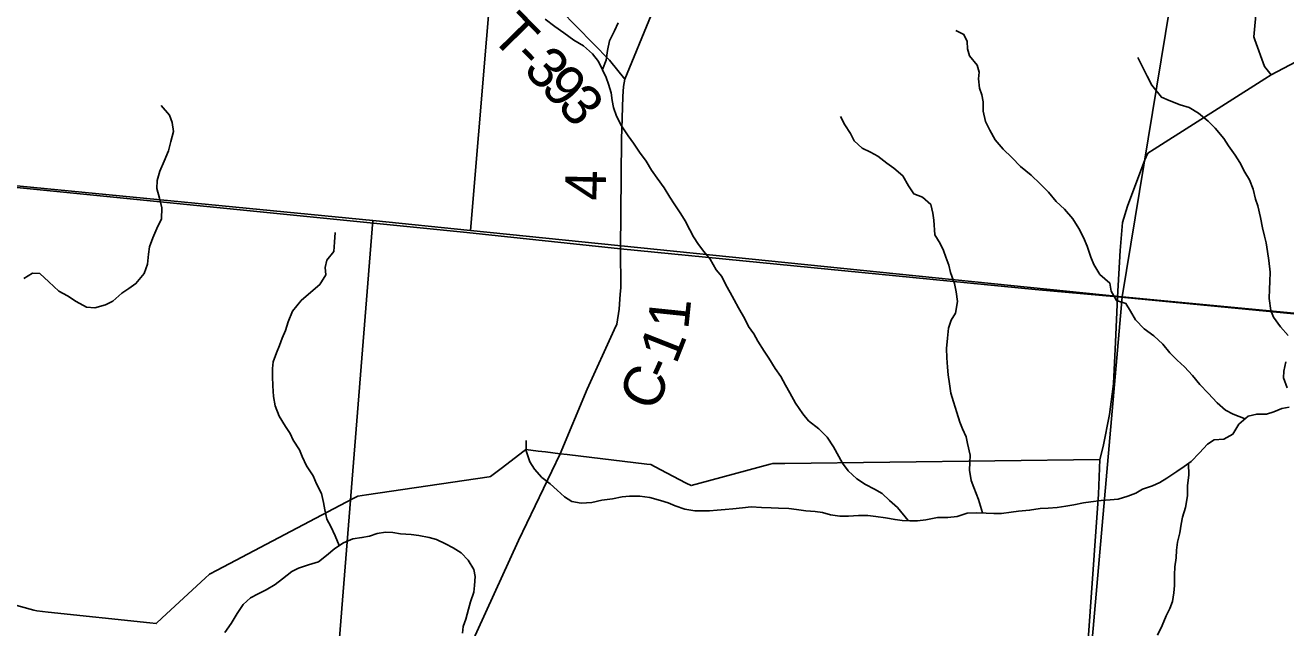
# Model space of a CAD drawing. Extents: x 0 to 42, y 0 to 22.
# Drawn here: x 2.271 to 3.149, y 16.454 to 16.874 of the extents above; entities that cross this region are included whole.
import ezdxf

# ---------------------------------------------------------------- set-up
doc = ezdxf.new("R2010")
doc.units = 0
for name, color, linetype in [('GM_X_County_Road', 7, 'Continuous'), ('GM_X_County_Road_Text', 7, 'Continuous'), ('GM_X_Minor_River', 7, 'Continuous'), ('GM_X_Section', 7, 'Continuous'), ('GM_X_Township_Road', 7, 'Continuous'), ('GM_X_Township_Road_Text', 7, 'Continuous'), ('GM_X_Unincorporated', 7, 'Continuous')]:
    doc.layers.add(name, color=color, linetype=linetype)

msp = doc.modelspace()

# ---------------------------------------------------------------- linework, layer by layer
at = {"layer": 'GM_X_County_Road'}
for points in [[(3.13844, 16.83963), (3.13371, 16.84527), (3.12716, 16.86391), (3.12645, 16.86593), (3.12717, 16.87363), (3.13317, 16.93756), (3.13328, 16.93883), (3.12484, 16.94043), (3.07632, 16.94963), (3.0777, 16.95929), (3.11773, 17.21473), (2.99607, 17.21011), (2.99103, 17.2099)], [(2.68511, 16.68671), (2.68545, 16.69114), (2.68536, 16.71812), (2.68602, 16.79453), (2.68687, 16.82435), (2.68744, 16.83145), (2.68835, 16.83654), (2.72497, 16.92595)], [(3.50756, 16.63162), (3.49853, 16.63934), (3.44232, 16.68624), (3.3385, 16.77134), (3.33566, 16.77384), (3.33464, 16.77987), (3.3173, 16.88212), (3.31708, 16.88339), (3.31183, 16.89018), (3.29373, 16.91364), (3.28943, 16.91921), (3.28257, 16.91567), (3.13844, 16.83963)], [(3.02838, 16.62254), (3.02865, 16.62454), (3.03004, 16.65342), (3.03147, 16.68469), (3.03318, 16.71722), (3.03483, 16.73675), (3.0384, 16.74804), (3.05044, 16.78036), (3.05248, 16.78486), (3.05688, 16.78766), (3.13403, 16.83681), (3.13844, 16.83963)], [(2.56825, 16.41433), (2.61413, 16.51522), (2.64333, 16.57563), (2.66209, 16.6207), (2.68086, 16.66198), (2.6826, 16.66583), (2.68431, 16.67637), (2.68511, 16.68671)], [(2.64333, 16.57563), (2.64821, 16.57505), (2.70371, 16.5684), (2.7065, 16.56806), (2.71301, 16.56465), (2.73101, 16.55521), (2.73439, 16.55344), (2.74052, 16.5551), (2.78958, 16.56836), (2.79129, 16.56882), (2.79967, 16.56886), (3.01914, 16.57163), (3.02134, 16.58071), (3.02575, 16.603), (3.02838, 16.62254)], [(2.18354, 16.49212), (2.27669, 16.46667), (2.27878, 16.4661), (2.28671, 16.46526), (2.35747, 16.45783), (2.36186, 16.45737), (2.36607, 16.46126), (2.39593, 16.48886), (2.39904, 16.49173), (2.40428, 16.49449), (2.49872, 16.5442), (2.50222, 16.54603), (2.50834, 16.54694), (2.59381, 16.55957), (2.59478, 16.5597), (2.60207, 16.56526), (2.61824, 16.57759), (2.61944, 16.5785), (2.62803, 16.57747), (2.63307, 16.57687), (2.64333, 16.57563)], [(3.15556, 16.07734), (3.11596, 16.08209), (3.10775, 16.08373), (3.09954, 16.08683), (3.08329, 16.09723), (3.06213, 16.11584), (3.04041, 16.13263), (3.01849, 16.15304), (2.99402, 16.18319), (2.97659, 16.20462), (2.94677, 16.24432), (2.92682, 16.26806), (2.92495, 16.27329), (2.92703, 16.28318), (2.9369, 16.30146), (2.94257, 16.3107), (2.94845, 16.31763), (2.99745, 16.36645), (3.0023, 16.37263), (3.00466, 16.37925), (3.00554, 16.38588), (3.00939, 16.42316), (3.01821, 16.54744), (3.01914, 16.57163)]]:
    msp.add_lwpolyline(points, dxfattribs=at)
at = {"layer": 'GM_X_Minor_River'}
for points in [[(2.88555, 16.52904), (2.87826, 16.53812), (2.87261, 16.54307), (2.86752, 16.54782), (2.86223, 16.55087), (2.85582, 16.55412), (2.84978, 16.55812), (2.84393, 16.56364), (2.83998, 16.56896), (2.83359, 16.58035), (2.82927, 16.58719), (2.82343, 16.59289), (2.81626, 16.59842), (2.8123, 16.60336), (2.80722, 16.61076), (2.80328, 16.61798), (2.80008, 16.6233), (2.79689, 16.62937), (2.79294, 16.63507), (2.78862, 16.6421), (2.78523, 16.64704), (2.7809, 16.65406), (2.77809, 16.65919), (2.77432, 16.66413), (2.77188, 16.66963), (2.76756, 16.67723), (2.76455, 16.68273), (2.76155, 16.68786), (2.75854, 16.69337), (2.75573, 16.69906), (2.75196, 16.70381), (2.74764, 16.71122), (2.74331, 16.71654), (2.73954, 16.72129), (2.73616, 16.72661), (2.73353, 16.73155), (2.73033, 16.73781), (2.72733, 16.74275), (2.72262, 16.74958), (2.71961, 16.75433), (2.71567, 16.76079), (2.71077, 16.76763), (2.70682, 16.77314), (2.70306, 16.77941), (2.69855, 16.78568), (2.69441, 16.79194), (2.69064, 16.79708), (2.68594, 16.80391), (2.68256, 16.81075), (2.68031, 16.81682), (2.67957, 16.82156), (2.67884, 16.82706), (2.67697, 16.83294), (2.67528, 16.83768), (2.67284, 16.84299), (2.66984, 16.84869), (2.6657, 16.8542), (2.65948, 16.85972), (2.65287, 16.86373), (2.6457, 16.86887), (2.63948, 16.87325), (2.63269, 16.8782)], [(2.67267, 16.84333), (2.67533, 16.84981), (2.6763, 16.85644), (2.67765, 16.86325), (2.68108, 16.87006), (2.68375, 16.87573)], [(3.12037, 16.59997), (3.11192, 16.60316), (3.10663, 16.60602), (3.10079, 16.61097), (3.09457, 16.61782), (3.08873, 16.6239), (3.08365, 16.63017), (3.07818, 16.63626), (3.0729, 16.64082), (3.06782, 16.64596), (3.06292, 16.65204), (3.0567, 16.65775), (3.0501, 16.66251), (3.04388, 16.66898), (3.0405, 16.67486), (3.0373, 16.68037), (3.03069, 16.68229), (3.02712, 16.68893), (3.026, 16.69443), (3.01922, 16.70052), (3.01489, 16.70736), (3.01283, 16.71248), (3.01021, 16.72007), (3.00777, 16.72614), (3.00439, 16.73241), (3.00026, 16.73924), (2.99461, 16.74589), (2.98876, 16.75122), (2.9833, 16.75768), (2.97765, 16.76358), (2.97124, 16.76967), (2.96389, 16.77576), (2.95786, 16.78203), (2.95183, 16.78774), (2.94618, 16.7942), (2.94242, 16.80104), (2.93941, 16.80711), (2.93793, 16.81413), (2.93795, 16.82076), (2.93683, 16.8255), (2.93534, 16.83024), (2.93461, 16.83669), (2.935, 16.84142), (2.9337, 16.84635), (2.92843, 16.85282), (2.92693, 16.85756), (2.92676, 16.86268), (2.92451, 16.86761), (2.91884, 16.87047)], [(3.15033, 16.65796), (3.14506, 16.66404), (3.13997, 16.67069), (3.13829, 16.67543), (3.137, 16.68378), (3.13721, 16.69022), (3.13742, 16.69552), (3.13782, 16.70215), (3.13691, 16.71011), (3.13598, 16.71637), (3.13487, 16.72243), (3.13375, 16.72717), (3.13245, 16.73286), (3.13096, 16.74007), (3.1291, 16.74822), (3.12761, 16.75296), (3.12593, 16.75998), (3.12331, 16.76643), (3.12011, 16.77175), (3.11654, 16.77839), (3.11335, 16.78352), (3.10864, 16.79017), (3.10544, 16.79511), (3.09942, 16.80233), (3.09452, 16.80728), (3.08792, 16.8128), (3.08131, 16.8168), (3.07508, 16.81853), (3.06733, 16.82159), (3.06205, 16.82407), (3.05527, 16.83225), (3.05208, 16.83851), (3.0487, 16.84553), (3.04569, 16.85161)], [(2.37309, 16.80624), (2.37122, 16.81137), (2.36538, 16.81821)], [(2.2696, 16.69769), (2.27567, 16.70145), (2.28078, 16.70124), (2.287, 16.69535), (2.29397, 16.68888), (2.3002, 16.68563), (2.30624, 16.68163), (2.31341, 16.67781), (2.31909, 16.67722), (2.32666, 16.67928), (2.33159, 16.68191), (2.33804, 16.68738), (2.34278, 16.69078), (2.34771, 16.69417), (2.35341, 16.70116), (2.35589, 16.70759), (2.35649, 16.7146), (2.35726, 16.71971), (2.35955, 16.72596), (2.36242, 16.73239), (2.36547, 16.7392), (2.36569, 16.74677), (2.3642, 16.7536), (2.36233, 16.76043), (2.36254, 16.76592), (2.36446, 16.77236), (2.36751, 16.77936), (2.37056, 16.78655), (2.3721, 16.79317), (2.37383, 16.79999), (2.37309, 16.80624)], [(2.93739, 16.53437), (2.93465, 16.54378), (2.93128, 16.55213), (2.92959, 16.55706), (2.9283, 16.56408), (2.92851, 16.56957), (2.92871, 16.57468), (2.92704, 16.58265), (2.92593, 16.58739), (2.92349, 16.59289), (2.92161, 16.59764), (2.91956, 16.60427), (2.91712, 16.61167), (2.91544, 16.61774), (2.91433, 16.62419), (2.9136, 16.63063), (2.91305, 16.63594), (2.91251, 16.64238), (2.91234, 16.64883), (2.91294, 16.65602), (2.91372, 16.66303), (2.91563, 16.66871), (2.91849, 16.67362), (2.92003, 16.68176), (2.91911, 16.6884), (2.91781, 16.69408), (2.91519, 16.70186), (2.91389, 16.70698), (2.91182, 16.71249), (2.91014, 16.71723), (2.90789, 16.72198), (2.90413, 16.72805), (2.90341, 16.73828), (2.90286, 16.74321), (2.90137, 16.74928), (2.89571, 16.75442), (2.88948, 16.75672), (2.88591, 16.76222), (2.88196, 16.76906), (2.87574, 16.77458), (2.87083, 16.77801), (2.86442, 16.78296), (2.85932, 16.78563), (2.85366, 16.78849), (2.848, 16.79344), (2.84538, 16.79876), (2.84161, 16.80465), (2.83842, 16.81053)], [(2.48931, 16.51167), (2.48646, 16.51838), (2.48346, 16.52484), (2.48064, 16.53015), (2.47934, 16.5366), (2.47841, 16.54172), (2.47692, 16.54798), (2.47354, 16.55462), (2.4711, 16.56031), (2.46659, 16.56715), (2.46359, 16.57361), (2.46172, 16.57835), (2.4572, 16.585), (2.45514, 16.58974), (2.45194, 16.59468), (2.44762, 16.60171), (2.44481, 16.60892), (2.44351, 16.61537), (2.44316, 16.62294), (2.4428, 16.62939), (2.44282, 16.63488), (2.44341, 16.63962), (2.4457, 16.64586), (2.4478, 16.65097), (2.44971, 16.65608), (2.452, 16.66137), (2.45391, 16.66743), (2.45678, 16.675), (2.46286, 16.68236), (2.46969, 16.68821), (2.47595, 16.69349), (2.47995, 16.7003), (2.47959, 16.70542), (2.48074, 16.71034), (2.48549, 16.71657), (2.48609, 16.72301), (2.48649, 16.72964)], [(3.14963, 16.62158), (3.147, 16.62842), (3.14721, 16.63315), (3.14875, 16.63959)], [(3.1509, 16.60794), (3.14598, 16.6072), (3.1403, 16.60476), (3.13518, 16.60326), (3.12837, 16.60329), (3.12251, 16.6018), (3.11586, 16.59614), (3.11187, 16.58933), (3.10542, 16.58576), (3.0988, 16.58521), (3.09406, 16.5822), (3.08855, 16.57635), (3.08285, 16.57012), (3.07793, 16.56673), (3.0728, 16.56315), (3.06579, 16.55863), (3.06086, 16.55561), (3.05574, 16.55336), (3.04893, 16.55092), (3.04419, 16.5481), (3.03869, 16.54604), (3.03188, 16.54398), (3.02639, 16.54362), (3.01996, 16.54308), (3.01295, 16.54215), (3.00766, 16.54142), (3.00103, 16.54012), (2.99554, 16.53919), (2.98949, 16.53827), (2.98324, 16.53772), (2.97757, 16.53755), (2.97018, 16.53625), (2.96243, 16.53572), (2.95732, 16.53498), (2.95069, 16.53405), (2.94521, 16.53389), (2.93991, 16.53429), (2.9331, 16.5345), (2.92667, 16.53415), (2.91985, 16.5319), (2.91323, 16.53117), (2.90604, 16.53119), (2.8979, 16.52952), (2.89223, 16.52897), (2.88674, 16.52899), (2.88145, 16.5292), (2.87653, 16.52979), (2.86991, 16.53095), (2.86311, 16.53192), (2.85744, 16.53251), (2.85101, 16.53254), (2.84401, 16.53219), (2.83795, 16.53221), (2.83153, 16.53318), (2.82605, 16.53472), (2.82094, 16.53549)], [(2.82094, 16.53549), (2.81432, 16.5359), (2.80789, 16.53687), (2.80241, 16.53746), (2.79523, 16.53768), (2.79012, 16.53789), (2.7835, 16.5381), (2.77631, 16.5387), (2.77026, 16.53796), (2.76345, 16.53723), (2.75815, 16.53687), (2.75266, 16.53632), (2.74736, 16.53596), (2.74244, 16.53579), (2.73715, 16.53581), (2.72997, 16.53698), (2.72335, 16.53928), (2.71844, 16.54138), (2.71315, 16.5431), (2.70578, 16.54503), (2.69879, 16.546), (2.6916, 16.54603), (2.68649, 16.54567), (2.67968, 16.54418), (2.6723, 16.54326), (2.66529, 16.54158), (2.65792, 16.54123), (2.6513, 16.54239), (2.6462, 16.54563), (2.64111, 16.5502), (2.63621, 16.55457), (2.63056, 16.55914), (2.62547, 16.56485), (2.62208, 16.56998), (2.61965, 16.57756), (2.61949, 16.58476)], [(3.08091, 16.56878), (3.08112, 16.56065), (3.08015, 16.55346), (3.08012, 16.54626), (3.07876, 16.53811), (3.07666, 16.53149), (3.07569, 16.52657), (3.07492, 16.52051), (3.07319, 16.51407), (3.07241, 16.50839), (3.0722, 16.50309), (3.07142, 16.49684), (3.07121, 16.49135), (3.07119, 16.48396), (3.0706, 16.47884), (3.06982, 16.47278), (3.06791, 16.46786), (3.06524, 16.46276), (3.06257, 16.45595), (3.05933, 16.44933)], [(2.4096, 16.45122), (2.41417, 16.45727), (2.41817, 16.46426), (2.42254, 16.47069), (2.42766, 16.47522), (2.43297, 16.47804), (2.43847, 16.48086), (2.44472, 16.48444), (2.44984, 16.4884), (2.45629, 16.49368), (2.46103, 16.49593), (2.46804, 16.49818), (2.47485, 16.50043), (2.48055, 16.50476), (2.48624, 16.50967), (2.49231, 16.51362), (2.49894, 16.51644), (2.50518, 16.51718), (2.51048, 16.51829), (2.51578, 16.51998), (2.52165, 16.5209), (2.52676, 16.52069), (2.53205, 16.51973), (2.53943, 16.51932), (2.54472, 16.51873), (2.55209, 16.51738), (2.557, 16.51584), (2.56342, 16.51279), (2.56871, 16.51011), (2.57437, 16.50649), (2.57927, 16.50155), (2.58322, 16.49509), (2.58396, 16.49016), (2.58356, 16.48391), (2.58316, 16.47918), (2.58087, 16.47255), (2.57933, 16.46744), (2.5776, 16.46044), (2.57569, 16.45533), (2.57511, 16.4506)]]:
    msp.add_lwpolyline(points, dxfattribs=at)
at = {"layer": 'GM_X_Section'}
for points in [[(2.6195, 17.19491), (3.12245, 17.21832), (3.03461, 16.68491), (2.58086, 16.73111)], [(3.12245, 17.21832), (3.34068, 17.13624), (3.55355, 17.11809), (3.48448, 16.64214), (3.03461, 16.68491)], [(2.58086, 16.73111), (3.03461, 16.68491), (2.98825, 16.15388), (2.46933, 16.19453), (2.51268, 16.73806)], [(3.48448, 16.64214), (3.5233, 16.63832), (3.48071, 16.11423), (2.98825, 16.15388), (3.03461, 16.68491)]]:
    msp.add_lwpolyline(points, close=True, dxfattribs=at)
at = {"layer": 'GM_X_Township_Road'}
for points in [[(2.1647, 16.77107), (2.57825, 16.72962), (2.68525, 16.71838), (2.97417, 16.68996), (3.03136, 16.68495), (3.42177, 16.64721), (3.49843, 16.6396), (3.92254, 16.6011), (3.99035, 16.5952), (4.03378, 16.59046), (4.40465, 16.549), (4.51047, 16.53717), (5.00039, 16.4852), (5.02016, 16.4831), (5.03045, 16.58367), (5.04866, 16.75825), (5.05771, 16.85926), (5.06939, 16.98984), (5.08351, 17.13677), (5.09562, 17.26276), (5.1195, 17.49729), (5.12853, 17.5887), (5.14624, 17.76794), (5.1674, 18.00102)], [(2.57411, 16.94892), (2.57783, 16.94397), (2.58703, 16.93584), (2.59444, 16.93067), (2.60208, 16.92573), (2.60927, 16.91966), (2.67757, 16.8498), (2.68835, 16.83654)], [(4.96357, 15.8483), (4.97611, 15.98164), (4.99947, 16.26251), (5.01446, 16.42239), (5.02016, 16.4831), (5.00039, 16.4852), (4.51047, 16.53717), (4.40465, 16.549), (4.03378, 16.59046), (3.99035, 16.5952), (3.92254, 16.6011), (3.49843, 16.6396), (3.42177, 16.64721), (3.03136, 16.68495), (2.97417, 16.68996), (2.68525, 16.71838), (2.57825, 16.72962), (2.1647, 16.77107), (2.1, 16.7767), (2.1, 14.1)]]:
    msp.add_lwpolyline(points, dxfattribs=at)
at = {"layer": 'GM_X_Unincorporated'}
for points in [[(2.1, 17.26831), (2.1, 16.77811), (2.51268, 16.73806), (2.58086, 16.73111), (2.6195, 17.19491)], [(2.1, 16.77811), (2.1, 16.22845), (2.46933, 16.19453), (2.51268, 16.73806)]]:
    msp.add_lwpolyline(points, close=True, dxfattribs=at)

# ---------------------------------------------------------------- texts
at = {"layer": 'GM_X_County_Road_Text'}
for s, rotation, p in [('4', 88.6368, (2.67482, 16.75166)), ('1', 84.08199, (2.73239, 16.66167)), ('1', 68.56821, (2.72402, 16.63724)), ('-', 65.65646, (2.71859, 16.62516)), ('C', 65.5247, (2.7089, 16.60386))]:
    msp.add_text(s, height=0.02841, rotation=rotation, dxfattribs=at).set_placement(p)
at = {"layer": 'GM_X_Township_Road_Text'}
for s, rotation, p in [('T', 314.33855, (2.59395, 16.86573)), ('-', 314.25892, (2.60876, 16.85056)), ('3', 313.95466, (2.61681, 16.84231)), ('9', 313.32898, (2.6288, 16.82987)), ('3', 310.83808, (2.64049, 16.81749))]:
    msp.add_text(s, height=0.02841, rotation=rotation, dxfattribs=at).set_placement(p)

doc.saveas('drawing.dxf')
